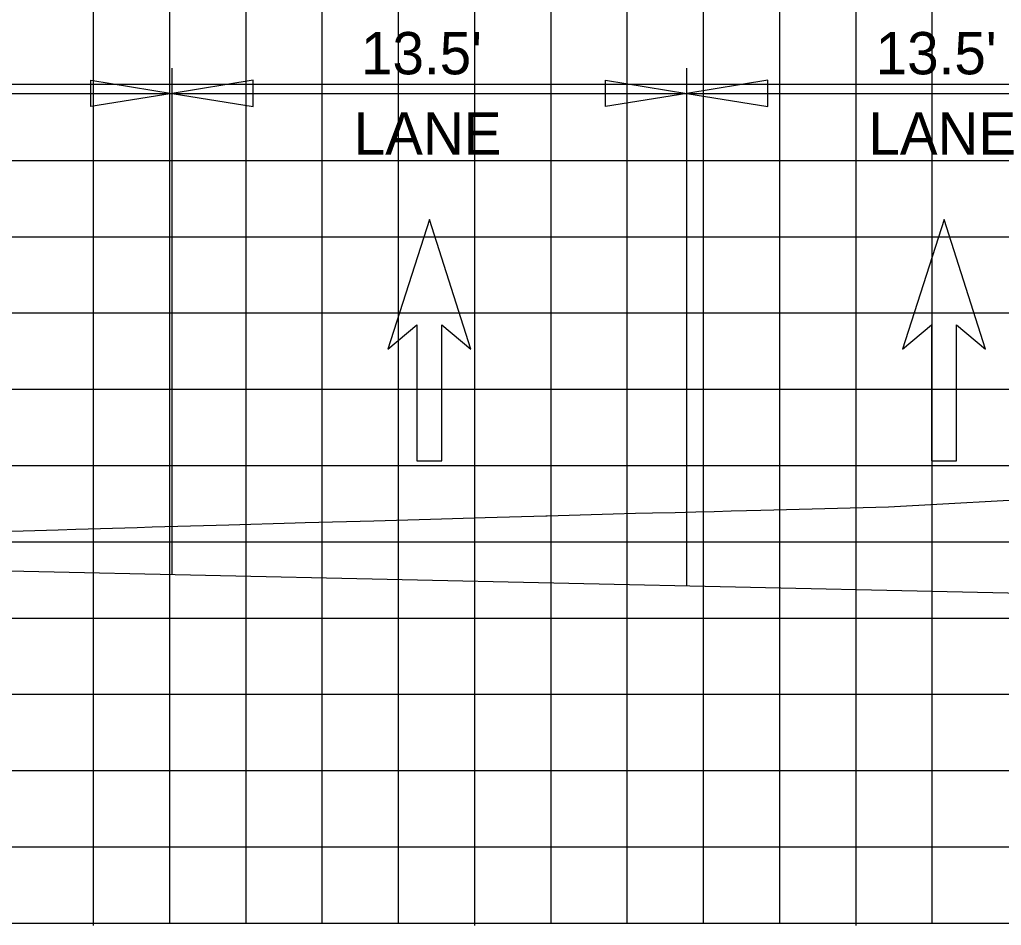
# Model space of a CAD drawing. Extents: x 2193008 to 2198143, y 1236112 to 1237864.
# Drawn here: x 2194960.92 to 2194986.67, y 1237258.05 to 1237281.8 of the extents above; entities that cross this region are included whole.
import ezdxf

# ---------------------------------------------------------------- set-up
doc = ezdxf.new("R2010")
doc.units = 0
for name, color, linetype in [('3', 7, 'Continuous'), ('60', 7, 'Continuous'), ('CL-CNST', 7, 'Continuous'), ('GSDIMS', 7, 'Continuous'), ('Level 28', 7, 'Continuous'), ('Level 55', 7, 'Continuous'), ('Level 62', 7, 'Continuous'), ('M-ROADS', 7, 'Continuous')]:
    doc.layers.add(name, color=color, linetype=linetype)

msp = doc.modelspace()

# ---------------------------------------------------------------- linework, layer by layer
at = {"layer": '3'}
for p, q in [((2194964.918, 1237267.243), (2194964.918, 1237280.525)), ((2194978.418, 1237266.946), (2194978.418, 1237280.525))]:
    msp.add_line(p, q, dxfattribs=at)
at = {"layer": '60'}
for p, q in [((2194892.86, 1237258.106), (2195022.86, 1237258.106)), ((2194962.86, 1237258.046), (2194962.86, 1237258.106)), ((2194972.86, 1237258.046), (2194972.86, 1237258.106)), ((2194982.86, 1237258.046), (2194982.86, 1237258.106))]:
    msp.add_line(p, q, dxfattribs=at)
at = {"layer": 'CL-CNST'}
msp.add_lwpolyline([(2195022.86, 1237269.861), (2195014.414, 1237267.045), (2195010.113, 1237266.873), (2195006.414, 1237266.725), (2195006.088, 1237266.725), (2195006.085, 1237266.725), (2195005.918, 1237266.225), (2195004.805, 1237266.314), (2195003.918, 1237266.385), (2194951.493, 1237267.538), (2194950.59, 1237267.558), (2194949.493, 1237267.582), (2194949.323, 1237268.082), (2194948.993, 1237268.082), (2194943.692, 1237268.294), (2194938.236, 1237268.512), (2194935.061, 1237268.561), (2194927.574, 1237268.677)], dxfattribs=at)
at = {"layer": 'GSDIMS'}
for p, q in [((2194951.493, 1237279.864), (2194964.918, 1237279.864)), ((2194964.918, 1237279.864), (2194978.418, 1237279.864)), ((2194978.418, 1237279.864), (2194991.918, 1237279.864))]:
    msp.add_line(p, q, dxfattribs=at)
for points in [[(2194964.918, 1237279.864), (2194962.79, 1237279.517), (2194962.79, 1237280.211)], [(2194964.918, 1237279.864), (2194967.046, 1237279.517), (2194967.046, 1237280.211)], [(2194978.418, 1237279.864), (2194976.29, 1237279.517), (2194976.29, 1237280.211)], [(2194978.418, 1237279.864), (2194980.546, 1237279.517), (2194980.546, 1237280.211)]]:
    msp.add_lwpolyline(points, close=True, dxfattribs=at)
at = {"layer": 'Level 28'}
for p, q in [((2194971.668, 1237276.554), (2194970.579, 1237273.156)), ((2194972.757, 1237273.156), (2194971.668, 1237276.554)), ((2194985.168, 1237276.554), (2194984.079, 1237273.156)), ((2194986.257, 1237273.156), (2194985.168, 1237276.554)), ((2194970.579, 1237273.156), (2194971.341, 1237273.796)), ((2194971.341, 1237273.796), (2194971.341, 1237270.225)), ((2194971.995, 1237270.225), (2194971.995, 1237273.796)), ((2194971.995, 1237273.796), (2194972.757, 1237273.156)), ((2194984.079, 1237273.156), (2194984.841, 1237273.796)), ((2194984.841, 1237273.796), (2194984.841, 1237270.225)), ((2194985.495, 1237270.225), (2194985.495, 1237273.796)), ((2194985.495, 1237273.796), (2194986.257, 1237273.156)), ((2194971.341, 1237270.225), (2194971.995, 1237270.225)), ((2194984.841, 1237270.225), (2194985.495, 1237270.225))]:
    msp.add_line(p, q, dxfattribs=at)
at = {"layer": 'Level 62'}
for p, q in [((2194962.86, 1237258.106), (2194962.86, 1237318.106)), ((2194964.86, 1237258.106), (2194964.86, 1237318.106)), ((2194966.86, 1237258.106), (2194966.86, 1237318.106)), ((2194968.86, 1237258.106), (2194968.86, 1237318.106)), ((2194970.86, 1237258.106), (2194970.86, 1237318.106)), ((2194972.86, 1237258.106), (2194972.86, 1237318.106)), ((2194974.86, 1237258.106), (2194974.86, 1237318.106)), ((2194976.86, 1237258.106), (2194976.86, 1237318.106)), ((2194978.86, 1237258.106), (2194978.86, 1237318.106)), ((2194980.86, 1237258.106), (2194980.86, 1237318.106)), ((2194982.86, 1237258.106), (2194982.86, 1237318.106)), ((2194984.86, 1237258.106), (2194984.86, 1237318.106)), ((2194892.86, 1237280.106), (2195022.86, 1237280.106)), ((2194892.86, 1237278.106), (2195022.86, 1237278.106)), ((2194892.86, 1237276.106), (2195022.86, 1237276.106)), ((2194892.86, 1237274.106), (2195022.86, 1237274.106)), ((2194892.86, 1237272.106), (2195022.86, 1237272.106)), ((2194892.86, 1237270.106), (2195022.86, 1237270.106)), ((2194892.86, 1237268.106), (2195022.86, 1237268.106)), ((2194892.86, 1237266.106), (2195022.86, 1237266.106)), ((2194892.86, 1237264.106), (2195022.86, 1237264.106)), ((2194892.86, 1237262.106), (2195022.86, 1237262.106)), ((2194892.86, 1237260.106), (2195022.86, 1237260.106)), ((2194892.86, 1237258.106), (2195022.86, 1237258.106))]:
    msp.add_line(p, q, dxfattribs=at)
at = {"layer": 'M-ROADS'}
msp.add_lwpolyline([(2194988.149, 1237269.261), (2194983.709, 1237269.009), (2194980.707, 1237268.934), (2194980.363, 1237268.925), (2194979.99, 1237268.916), (2194979.585, 1237268.905), (2194979.141, 1237268.894), (2194978.654, 1237268.883), (2194978.118, 1237268.869), (2194977.524, 1237268.854), (2194977.076, 1237268.843), (2194976.49, 1237268.826), (2194974.755, 1237268.778), (2194974.723, 1237268.778), (2194973.135, 1237268.733), (2194971.695, 1237268.694), (2194970.215, 1237268.65), (2194968.413, 1237268.599), (2194968.144, 1237268.591), (2194966.406, 1237268.542), (2194966.074, 1237268.532), (2194964.399, 1237268.485), (2194964.003, 1237268.473), (2194962.394, 1237268.427), (2194961.933, 1237268.413), (2194960.388, 1237268.369)], dxfattribs=at)

# ---------------------------------------------------------------- texts
at = {"layer": 'Level 55'}
for s, p in [("13.5'", (2194969.875, 1237280.364)), ("13.5'", (2194983.375, 1237280.364)), ('LANE', (2194969.682, 1237278.254)), ('LANE', (2194983.182, 1237278.254))]:
    msp.add_text(s, height=1.1105, dxfattribs=at).set_placement(p)

doc.saveas('drawing.dxf')
